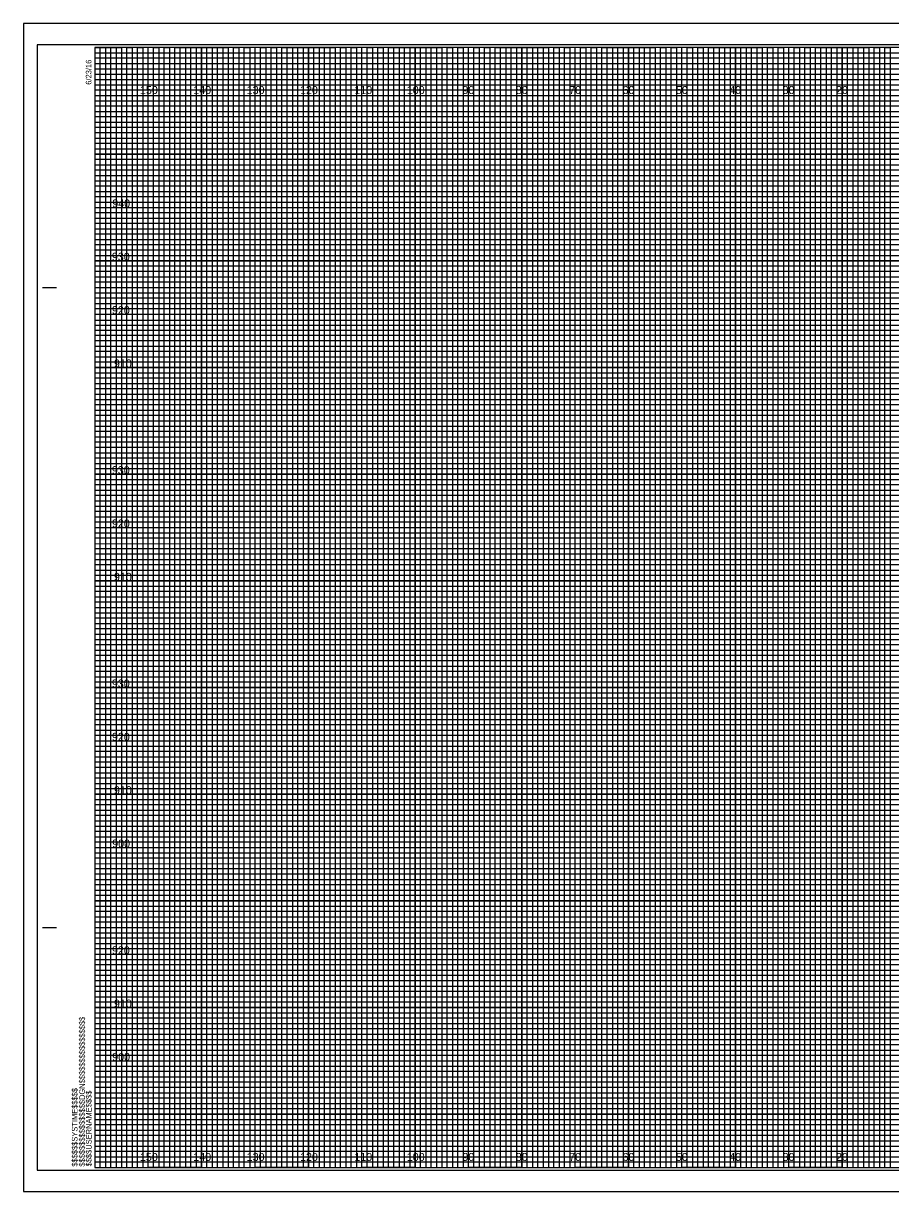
# Model space of a CAD drawing. Extents: x -13 to 323, y 216 to 434.
# Drawn here: x -13.4 to 149.1, y 215.5 to 434.5 of the extents above; entities that cross this region are included whole.
import ezdxf

# ---------------------------------------------------------------- set-up
doc = ezdxf.new("R2010")
doc.units = 0
for name, color, linetype in [('Prop XS Elevation Labels', 7, 'Continuous'), ('Prop XS Label Text', 7, 'Continuous'), ('Scratch_Level_1', 7, 'Continuous'), ('Scratch_Level_4', 7, 'Continuous'), ('Sheet Cross Section CELL', 7, 'Continuous'), ('Sheet Cross Section Grid Minor 1 CELL', 7, 'Continuous'), ('Sheet Cross Section Grid Minor 2 CELL', 7, 'Continuous'), ('Sheet Cutting Line CELL', 7, 'Continuous'), ('Sheet DOT Grid CELL', 7, 'Continuous'), ('Sheet Plot Border Inside CELL', 7, 'Continuous'), ('Sheet Plot Border Outside CELL', 7, 'Continuous')]:
    doc.layers.add(name, color=color, linetype=linetype)

msp = doc.modelspace()

# ---------------------------------------------------------------- linework, layer by layer
at = {"layer": 'Prop XS Label Text'}
for points in [[(0, 430), (5, 430), (5, 220), (15, 220), (15, 430), (25, 430), (25, 220), (35, 220), (35, 430), (45, 430), (45, 220), (55, 220), (55, 430), (65, 430), (65, 220), (75, 220), (75, 430), (85, 430), (85, 220), (95, 220), (95, 430), (105, 430), (105, 220), (115, 220), (115, 430), (125, 430), (125, 220), (135, 220), (135, 430), (145, 430), (145, 220), (155, 220)], [(0, 425), (275, 425)], [(0, 405), (320, 405), (320, 415), (0, 415)], [(0, 385), (320, 385), (320, 395), (0, 395)], [(0, 365), (320, 365), (320, 375), (0, 375)], [(0, 345), (320, 345), (320, 355), (0, 355)], [(0, 325), (320, 325), (320, 335), (0, 335)], [(0, 305), (320, 305), (320, 315), (0, 315)], [(0, 285), (320, 285), (320, 295), (0, 295)], [(0, 265), (320, 265), (320, 275), (0, 275)], [(0, 245), (320, 245), (320, 255), (0, 255)], [(0, 225), (320, 225), (320, 235), (0, 235)]]:
    msp.add_lwpolyline(points, dxfattribs=at)
at = {"layer": 'Scratch_Level_4'}
for p, q in [((10, 430), (0, 430)), ((10, 220), (10, 430)), ((30, 430), (20, 430)), ((20, 430), (20, 220)), ((30, 220), (30, 430)), ((50, 430), (40, 430)), ((40, 430), (40, 220)), ((50, 220), (50, 430)), ((70, 430), (60, 430)), ((60, 430), (60, 220)), ((70, 220), (70, 430)), ((90, 430), (80, 430)), ((80, 430), (80, 220)), ((90, 220), (90, 430)), ((110, 430), (100, 430)), ((100, 430), (100, 220)), ((110, 220), (110, 430)), ((130, 430), (120, 430)), ((120, 430), (120, 220)), ((130, 220), (130, 430)), ((150, 430), (140, 430)), ((140, 430), (140, 220)), ((20, 220), (10, 220)), ((40, 220), (30, 220)), ((60, 220), (50, 220)), ((80, 220), (70, 220)), ((100, 220), (90, 220)), ((120, 220), (110, 220)), ((140, 220), (130, 220))]:
    msp.add_line(p, q, dxfattribs=at)
for points in [[(0, 420), (320, 420), (320, 410), (0, 410)], [(0, 400), (320, 400), (320, 390), (0, 390)], [(0, 380), (320, 380), (320, 370), (0, 370)], [(0, 360), (320, 360), (320, 350), (0, 350)], [(0, 340), (320, 340), (320, 330), (0, 330)], [(0, 320), (320, 320), (320, 310), (0, 310)], [(0, 300), (320, 300), (320, 290), (0, 290)], [(0, 280), (320, 280), (320, 270), (0, 270)], [(0, 260), (320, 260), (320, 250), (0, 250)], [(0, 240), (320, 240), (320, 230), (0, 230)]]:
    msp.add_lwpolyline(points, dxfattribs=at)
at = {"layer": 'Sheet Cross Section CELL'}
for p, q in [((-9.8, 385), (-7.3, 385)), ((-9.7, 385), (-7.2, 385)), ((-9.8, 265), (-7.3, 265)), ((-9.7, 265), (-7.2, 265)), ((0, 220), (0, 220)), ((0, 220), (0, 220)), ((0, 220), (0, 220)), ((0, 220), (0, 220)), ((0, 220), (0, 220)), ((0, 220), (0, 220)), ((0, 220), (0, 220))]:
    msp.add_line(p, q, dxfattribs=at)
msp.add_lwpolyline([(320, 430), (0, 430), (0, 220), (320, 220)], close=True, dxfattribs=at)
at = {"layer": 'Sheet Cross Section Grid Minor 1 CELL'}
for p, q in [((0, 429), (260, 429)), ((260, 427.98), (0, 427.98)), ((0, 427.98), (0, 427)), ((0, 427), (260, 427)), ((260, 425.89), (0, 425.89)), ((0, 425.89), (0, 424)), ((0, 424), (320, 424))]:
    msp.add_line(p, q, dxfattribs=at)
for points in [[(0, 423), (270, 423), (320, 423), (320, 422), (0, 422)], [(0, 421), (320, 421), (320, 419), (0, 419)], [(0, 418), (320, 418), (320, 417), (0, 416.98)], [(0, 416), (320, 416), (320, 414), (0, 414)], [(0, 413), (320, 413), (320, 412), (0, 412)], [(0, 411), (320, 411), (320, 409), (0, 409)], [(0, 408), (320, 408), (320, 407), (0, 407)], [(0, 406), (320, 406), (320, 404), (0, 404)], [(0, 403), (320, 403), (320, 402), (0, 402)], [(0, 401), (320, 401), (320, 399), (0, 399)], [(0, 398), (320, 398), (320, 397), (0, 397)], [(0, 396), (320, 396), (320, 393.95), (320, 393), (320, 392), (0, 392)], [(0, 394), (320, 394), (320, 393), (0, 393)], [(0, 391), (320, 391), (320, 389), (0, 389.03)], [(0, 389.03), (320, 389), (320, 388), (0, 388)], [(0, 387), (320, 387), (320, 386), (0, 386)], [(0, 384), (320, 384), (320, 383), (0, 383)], [(0, 382), (320, 382), (320, 381), (0, 381)], [(-0.07, 378.89), (320, 378.89), (320, 377.88), (-0.07, 377.88)], [(0, 377), (320, 377), (320, 376), (0, 376)], [(0, 374), (320, 374), (320, 373), (0, 373)], [(0, 372), (320, 372), (320, 371), (0, 371)], [(0, 369), (320, 369), (320, 368), (0, 368)], [(0, 367), (320, 367), (320, 366), (0, 366)], [(0, 364), (320, 364), (320, 363), (0, 363)], [(0, 362), (320, 362), (320, 361), (0, 361)], [(0, 359), (320, 359), (319.99, 357.98), (0, 358)], [(0, 357), (320, 357), (320, 356), (0, 356)], [(0, 354), (320, 354), (320, 353), (0, 353)], [(0, 352), (320, 352), (320, 351), (0, 351)], [(0, 349), (320, 349), (320, 348), (0, 348)], [(0, 347), (320, 347), (320, 346), (0, 346)], [(0, 344), (320, 344), (320, 343), (0, 343)], [(0, 342), (320, 342), (320, 341), (0, 341)], [(0, 339), (320, 339), (320, 338), (0, 338)], [(0, 336.99), (320.07, 336.91), (320, 336), (0, 336)], [(0, 334), (320, 334), (320, 333), (0, 333)], [(0, 332), (320, 332), (320, 331), (0, 331)], [(0, 329), (320, 329), (320, 328), (0, 328)], [(0, 327), (320, 327), (320, 326), (0, 326)], [(0, 324), (320, 324), (320, 323), (0, 323)], [(0, 322), (320, 322), (320, 321), (0, 321)], [(0, 319), (320, 319), (320, 318), (0, 318)], [(0, 317), (320, 317), (320, 316), (0, 316)], [(0, 314), (320, 314), (320, 313), (0, 313)], [(0, 312), (320, 312), (320, 311), (0, 311)], [(0, 309), (320, 309), (320, 308), (0, 308)], [(0, 307), (320, 307), (320, 306), (0, 306)], [(0, 304), (320, 304), (320, 303), (0, 303)], [(0, 302), (320, 302), (320, 301), (0, 301)], [(0, 299), (320, 299), (319.99, 297.98), (0, 298)], [(0, 297), (320, 297), (320, 296), (0, 296)], [(0, 294), (320, 294), (320, 293), (0, 293)], [(0, 292), (320, 292), (320, 291), (0, 291)], [(0, 289), (320, 289), (320, 288), (0, 288)], [(0, 287), (320, 287), (320, 286), (0, 286)], [(0, 284), (320, 284), (320, 283), (0, 283)], [(0, 282), (320, 282), (320, 281), (0, 281)], [(0, 279), (320, 279), (320, 278), (0, 278)], [(0, 276.99), (320.07, 276.91), (320, 276), (0, 276)], [(0, 274), (320, 274), (320, 273), (0, 273)], [(0, 272), (320, 272), (320, 271), (0, 271)], [(0, 269), (320, 269), (320, 268), (0, 268)], [(0, 267), (320, 267), (320, 266), (0, 266)], [(0, 264), (320, 264), (320, 263), (0, 263)], [(0, 262), (320, 262), (320, 261), (0, 261)], [(0, 259), (320, 259), (320, 258), (0, 258)], [(0, 257), (320, 257), (320, 256), (0, 256)], [(0, 254), (320, 254), (320, 253), (0, 253)], [(0, 252), (320, 252), (320, 251), (0, 251)], [(0, 249), (320, 249), (320, 248), (0, 248)], [(0, 247), (320, 247), (320, 246), (0, 246)], [(0, 244), (320, 244), (320, 243), (0, 243)], [(0, 242), (320, 242), (320, 241), (0, 241)], [(0, 239), (320, 239), (320, 238), (0, 238)], [(0, 237), (320, 237), (320, 236), (0, 236)], [(0, 234), (320, 234), (320, 233), (0, 233)], [(0, 232), (320, 232), (320, 231), (0, 231)], [(0, 229), (320, 229), (320, 228), (0, 228)], [(0, 227), (320, 227), (320, 226), (0, 226)], [(0, 224), (320, 224), (320, 223), (0, 223)], [(0, 222), (320, 222), (320, 221), (0, 221)]]:
    msp.add_lwpolyline(points, dxfattribs=at)
at = {"layer": 'Sheet Cross Section Grid Minor 2 CELL'}
for points in [[(0, 220), (1, 220), (1, 430), (2, 430), (2, 220)], [(2, 220), (3, 220), (3, 430), (4, 430), (4, 220)], [(5, 220), (6, 220), (6, 430), (7, 430), (7, 220)], [(7, 220), (8, 220), (8, 430), (9, 430), (9, 220)], [(10, 220), (11, 220), (11, 430), (12, 430), (12, 220)], [(12, 220), (13, 220), (13, 430), (14, 430), (14, 220)], [(15, 220), (16, 220), (16, 430), (17, 430), (17, 220)], [(17, 220), (18, 220), (18, 430), (19, 430), (19, 220)], [(20, 220), (21, 220), (21, 430), (22, 430), (22, 220)], [(22, 220), (23, 220), (23, 430), (24, 430), (24, 220)], [(25, 220), (26, 220), (26, 430), (27, 430), (27, 220)], [(27, 220), (28, 220), (28, 430), (29, 430), (29, 220)], [(30, 220), (31, 220), (31, 430), (32, 430), (32, 220)], [(32, 220), (33, 220), (33, 430), (34, 430), (34, 220)], [(35, 220), (36, 220), (36, 430), (37, 430), (37, 220)], [(37, 220), (38, 220), (38, 430), (39, 430), (39, 220)], [(40, 220), (41, 220), (41, 430), (42, 430), (42, 220)], [(42, 220), (43, 220), (43, 430), (44, 430), (44, 220)], [(45, 220), (46, 220), (46, 430), (47, 430), (47, 220)], [(47, 220), (48, 220), (48, 430), (49, 430), (49, 220)], [(50, 220), (51, 220), (51, 430), (52, 430), (52, 220)], [(52, 220), (53, 220), (53, 430), (54, 430), (54, 220)], [(55, 220), (56, 220), (56, 430), (57, 430), (57, 220)], [(57, 220), (58, 220), (58, 430), (59, 430), (59, 220)], [(60, 220), (61, 220), (61, 430), (62, 430), (62, 220)], [(62, 220), (63, 220), (63, 430), (64, 430), (64, 220)], [(65, 220), (66, 220), (66, 430), (67, 430), (67, 220)], [(67, 220), (68, 220), (68, 430), (69, 430), (69, 220)], [(70, 220), (71, 220), (71, 430), (72, 430), (72, 220)], [(72, 220), (73, 220), (73, 430), (74, 430), (74, 220)], [(75, 220), (76, 220), (76, 430), (77, 430), (77, 220)], [(77, 220), (78, 220), (78, 430), (79, 430), (79, 220)], [(80, 220), (81, 220), (81, 430), (82, 430), (82, 220)], [(82, 220), (83, 220), (83, 430), (84, 430), (84, 220)], [(85, 220), (86, 220), (86, 430), (87, 430), (87, 220)], [(87, 220), (88, 220), (88, 430), (89, 430), (89, 220)], [(90, 220), (91, 220), (91, 430), (92, 430), (92, 220)], [(92, 220), (93, 220), (93, 430), (94, 430), (94, 220)], [(95, 220), (96, 220), (96, 430), (97, 430), (97, 220)], [(97, 220), (98, 220), (98, 430), (99, 430), (99, 220)], [(100, 220), (101, 220), (101, 430), (102, 430), (102, 220)], [(102, 220), (103, 220), (103, 430), (104, 430), (104, 220)], [(105, 220), (106, 220), (106, 430), (107, 430), (107, 220)], [(107, 220), (108, 220), (108, 430), (109, 430), (109, 220)], [(110, 220), (111, 220), (111, 430), (112, 430), (112, 220)], [(112, 220), (113, 220), (113, 430), (114, 430), (114, 220)], [(115, 220), (116, 220), (116, 430), (117, 430), (117, 220)], [(117, 220), (118, 220), (118, 430), (119, 430), (119, 220)], [(120, 220), (121, 220), (121, 430), (122, 430), (122, 220)], [(122, 220), (123, 220), (123, 430), (124, 430), (124, 220)], [(125, 220), (126, 220), (126, 430), (127, 430), (127, 220)], [(127, 220), (128, 220), (128, 430), (129, 430), (129, 220)], [(130, 220), (131, 220), (131, 430), (132, 430), (132, 220)], [(132, 220), (133, 220), (133, 430), (134, 430), (134, 220)], [(135, 220), (136, 220), (136, 430), (137, 430), (137, 220)], [(137, 220), (138, 220), (138, 430), (139, 430), (139, 220)], [(140, 220), (141, 220), (141, 430), (142, 430), (142, 220)], [(142, 220), (143, 220), (143, 430), (144, 430), (144, 220)], [(145, 220), (146, 220), (146, 430), (147, 430), (147, 220)], [(147, 220), (148, 220), (148, 430), (149, 430), (149, 220)]]:
    msp.add_lwpolyline(points, dxfattribs=at)
at = {"layer": 'Sheet Cutting Line CELL'}
for p, q in [((323.3, 434.5), (-13.4, 434.5)), ((-13.4, 434.5), (-13.4, 215.5)), ((-13.4, 215.5), (323.3, 215.5))]:
    msp.add_line(p, q, dxfattribs=at)
at = {"layer": 'Sheet DOT Grid CELL'}
for p, q in [((10, 220), (10, 430)), ((20, 220), (20, 430)), ((30, 220), (30, 430)), ((40, 220), (40, 430)), ((50, 220), (50, 430)), ((60, 220), (60, 430)), ((70, 220), (70, 430)), ((80, 220), (80, 430)), ((90, 220), (90, 430)), ((100, 220), (100, 430)), ((110, 220), (110, 430)), ((120, 220), (120, 430)), ((130, 220), (130, 430)), ((140, 220), (140, 430)), ((0, 420), (320, 420)), ((0, 410), (320, 410)), ((0, 400), (320, 400)), ((0, 390), (320, 390)), ((0, 380), (320, 380)), ((0, 370), (320, 370)), ((0, 360), (320, 360)), ((0, 350), (320, 350)), ((0, 340), (320, 340)), ((0, 330), (320, 330)), ((0, 320), (320, 320)), ((0, 310), (320, 310)), ((0, 300), (320, 300)), ((0, 290), (320, 290)), ((0, 280), (320, 280)), ((0, 270), (320, 270)), ((0, 260), (320, 260)), ((0, 250), (320, 250)), ((0, 240), (320, 240)), ((0, 230), (320, 230))]:
    msp.add_line(p, q, dxfattribs=at)
at = {"layer": 'Sheet Plot Border Inside CELL'}
msp.add_lwpolyline([(-10.8, 219.5), (322.4, 219.5), (322.4, 430.5), (-10.8, 430.5)], close=True, dxfattribs=at)
at = {"layer": 'Sheet Plot Border Outside CELL'}
msp.add_lwpolyline([(-13.4, 215.5), (323.3, 215.5), (323.3, 434.5), (-13.4, 434.5)], close=True, dxfattribs=at)

# ---------------------------------------------------------------- texts
at = {"layer": 'Prop XS Elevation Labels'}
for s, p in [('940', (3.26, 400)), ('930', (3.18, 390)), ('920', (3.19, 380)), ('910', (3.57, 370)), ('930', (3.18, 350)), ('920', (3.19, 340)), ('910', (3.57, 330)), ('930', (3.18, 310)), ('920', (3.19, 300)), ('910', (3.57, 290)), ('900', (3.24, 280)), ('920', (3.19, 260)), ('910', (3.57, 250)), ('900', (3.24, 240))]:
    msp.add_text(s, height=1.5, dxfattribs=at).set_placement(p)
at = {"layer": 'Scratch_Level_1'}
for s, p in [('150', (8.44, 421.25)), ('140', (18.44, 421.25)), ('130', (28.44, 421.25)), ('120', (38.44, 421.25)), ('110', (48.62, 421.25)), ('100', (58.44, 421.25)), ('90', (68.86, 421.25)), ('80', (78.86, 421.25)), ('70', (88.86, 421.25)), ('60', (98.86, 421.25)), ('50', (108.86, 421.25)), ('40', (118.86, 421.25)), ('30', (128.86, 421.25)), ('20', (138.86, 421.25)), ('150', (8.44, 221.25)), ('140', (18.44, 221.25)), ('130', (28.44, 221.25)), ('120', (38.44, 221.25)), ('110', (48.62, 221.25)), ('100', (58.44, 221.25)), ('90', (68.86, 221.25)), ('80', (78.86, 221.25)), ('70', (88.86, 221.25)), ('60', (98.86, 221.25)), ('50', (108.86, 221.25)), ('40', (118.86, 221.25)), ('30', (128.86, 221.25)), ('20', (138.86, 221.25))]:
    msp.add_text(s, height=1.5, dxfattribs=at).set_placement(p)
at = {"layer": 'Sheet Cross Section CELL'}
for s, p in [('6/23/16', (-0.65, 423)), ('$$$$$$$$$$$$$$$$DGN$$$$$$$$$$$$$$$$', (-1.88, 220.18)), ('$$$$$$SYSTIME$$$$$', (-3.26, 220.18)), ('$$$$USERNAME$$$$', (-0.62, 220.23))]:
    msp.add_text(s, height=1.05, rotation=90, dxfattribs=at).set_placement(p)

doc.saveas('drawing.dxf')
